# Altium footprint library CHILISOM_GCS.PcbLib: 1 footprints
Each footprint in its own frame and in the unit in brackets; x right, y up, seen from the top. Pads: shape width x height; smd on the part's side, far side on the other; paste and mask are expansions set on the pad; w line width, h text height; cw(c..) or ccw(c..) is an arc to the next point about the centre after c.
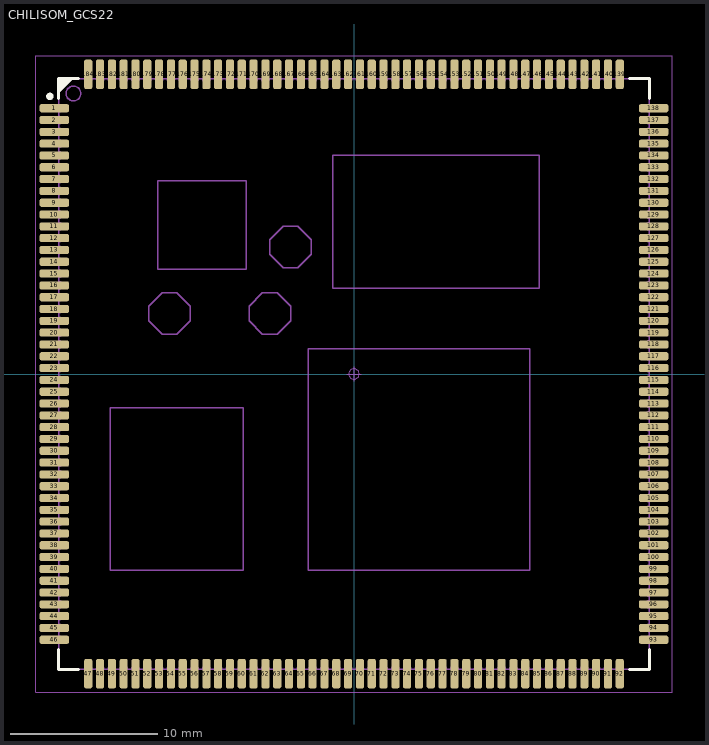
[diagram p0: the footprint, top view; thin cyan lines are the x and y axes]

## CHILISOM_GCS22 [mm]
height 2.7
pads (184):
  rrect50% 2x0.55 smd: 1(-20.3,18) 2(-20.3,17.2) 3(-20.3,16.4) 4(-20.3,15.6) 5(-20.3,14.8) 6(-20.3,14) 7(-20.3,13.2) 8(-20.3,12.4) 9(-20.3,11.6) 10(-20.3,10.8) 11(-20.3,10) 12(-20.3,9.2) 13(-20.3,8.4) 14(-20.3,7.6) 15(-20.3,6.8) 16(-20.3,6) 17(-20.3,5.2) 18(-20.3,4.4) 19(-20.3,3.6) 20(-20.3,2.8) 21(-20.3,2) 22(-20.3,1.2) 23(-20.3,0.4) 24(-20.3,-0.4) 25(-20.3,-1.2) 26(-20.3,-2) 27(-20.3,-2.8) 28(-20.3,-3.6) 29(-20.3,-4.4) 30(-20.3,-5.2) 31(-20.3,-6) 32(-20.3,-6.8) 33(-20.3,-7.6) 34(-20.3,-8.4) 35(-20.3,-9.2) 36(-20.3,-10) 37(-20.3,-10.8) 38(-20.3,-11.6) 39(-20.3,-12.4) 40(-20.3,-13.2) 41(-20.3,-14) 42(-20.3,-14.8) 43(-20.3,-15.6) 44(-20.3,-16.4) 45(-20.3,-17.2) 46(-20.3,-18) 93(20.3,-18) 94(20.3,-17.2) 95(20.3,-16.4) 96(20.3,-15.6) 97(20.3,-14.8) 98(20.3,-14) 99(20.3,-13.2) 100(20.3,-12.4) 101(20.3,-11.6) 102(20.3,-10.8) 103(20.3,-10) 104(20.3,-9.2) 105(20.3,-8.4) 106(20.3,-7.6) 107(20.3,-6.8) 108(20.3,-6) 109(20.3,-5.2) 110(20.3,-4.4) 111(20.3,-3.6) 112(20.3,-2.8) 113(20.3,-2) 114(20.3,-1.2) 115(20.3,-0.4) 116(20.3,0.4) 117(20.3,1.2) 118(20.3,2) 119(20.3,2.8) 120(20.3,3.6) 121(20.3,4.4) 122(20.3,5.2) 123(20.3,6) 124(20.3,6.8) 125(20.3,7.6) 126(20.3,8.4) 127(20.3,9.2) 128(20.3,10) 129(20.3,10.8) 130(20.3,11.6) 131(20.3,12.4) 132(20.3,13.2) 133(20.3,14) 134(20.3,14.8) 135(20.3,15.6) 136(20.3,16.4) 137(20.3,17.2) 138(20.3,18)
  rrect50% 0.55x2 smd: 47(-18,-20.3) 48(-17.2,-20.3) 49(-16.4,-20.3) 50(-15.6,-20.3) 51(-14.8,-20.3) 52(-14,-20.3) 53(-13.2,-20.3) 54(-12.4,-20.3) 55(-11.6,-20.3) 56(-10.8,-20.3) 57(-10,-20.3) 58(-9.2,-20.3) 59(-8.4,-20.3) 60(-7.6,-20.3) 61(-6.8,-20.3) 62(-6,-20.3) 63(-5.2,-20.3) 64(-4.4,-20.3) 65(-3.6,-20.3) 66(-2.8,-20.3) 67(-2,-20.3) 68(-1.2,-20.3) 69(-0.4,-20.3) 70(0.4,-20.3) 71(1.2,-20.3) 72(2,-20.3) 73(2.8,-20.3) 74(3.6,-20.3) 75(4.4,-20.3) 76(5.2,-20.3) 77(6,-20.3) 78(6.8,-20.3) 79(7.6,-20.3) 80(8.4,-20.3) 81(9.2,-20.3) 82(10,-20.3) 83(10.8,-20.3) 84(11.6,-20.3) 85(12.4,-20.3) 86(13.2,-20.3) 87(14,-20.3) 88(14.8,-20.3) 89(15.6,-20.3) 90(16.4,-20.3) 91(17.2,-20.3) 92(18,-20.3) 139(18,20.3) 140(17.2,20.3) 141(16.4,20.3) 142(15.6,20.3) 143(14.8,20.3) 144(14,20.3) 145(13.2,20.3) 146(12.4,20.3) 147(11.6,20.3) 148(10.8,20.3) 149(10,20.3) 150(9.2,20.3) 151(8.4,20.3) 152(7.6,20.3) 153(6.8,20.3) 154(6,20.3) 155(5.2,20.3) 156(4.4,20.3) 157(3.6,20.3) 158(2.8,20.3) 159(2,20.3) 160(1.2,20.3) 161(0.4,20.3) 162(-0.4,20.3) 163(-1.2,20.3) 164(-2,20.3) 165(-2.8,20.3) 166(-3.6,20.3) 167(-4.4,20.3) 168(-5.2,20.3) 169(-6,20.3) 170(-6.8,20.3) 171(-7.6,20.3) 172(-8.4,20.3) 173(-9.2,20.3) 174(-10,20.3) 175(-10.8,20.3) 176(-11.6,20.3) 177(-12.4,20.3) 178(-13.2,20.3) 179(-14,20.3) 180(-14.8,20.3) 181(-15.6,20.3) 182(-16.4,20.3) 183(-17.2,20.3) 184(-18,20.3)
Top Overlay:
  circle w0.25: c-20.6,18.8 r0.125
  region: -20,20 -20,19 -19,20
  lines w0.2: -20,-18.65 -20,-20 -18.65,-20 ; -20,18.65 -20,20 -18.65,20 ; 18.65,-20 20,-20 20,-18.65 ; 18.65,20 20,20 20,18.65
Mechanical 13:
  drawing of 413 lines, arcs and shapes, not listed
  text ".Comment" at -2.4,2.3 h0.5
  text ".Designator" at -20,20.2 h0.5
Mechanical 15:
  circle w0.05: c0,0 r0.35
  lines w0.05: -0.5,0 0.5,0 ; 0,-0.5 0,0.5 ; -21.55,-21.55 -21.55,21.55 21.55,21.55 21.55,-21.55 -21.55,-21.55
3D body "ChiliSOM.step": height 2.6, standoff -0.03, extent -20,-20 20,20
